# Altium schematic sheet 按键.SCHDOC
size A4
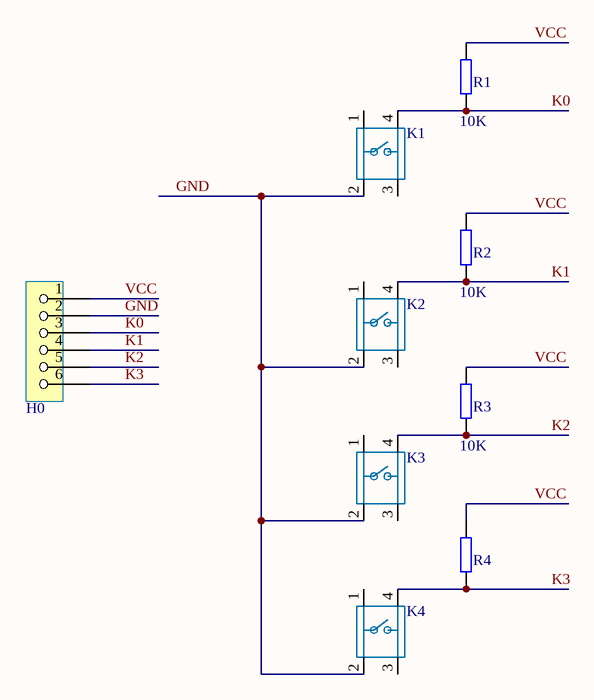
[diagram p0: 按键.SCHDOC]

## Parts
H0  DIS6  [DIS6]  (value not drawn)
K1  BUTTON  [BUTTON]  (value not drawn)
K2  BUTTON  [BUTTON]  (value not drawn)
K3  BUTTON  [BUTTON]  (value not drawn)
K4  BUTTON  [BUTTON]  (value not drawn)
R1  RESIS  [resistor-0.4]  (value not drawn)
R2  RESIS  [resistor-0.4]  (value not drawn)
R3  RESIS  [resistor-0.4]  (value not drawn)
R4  RESIS  [resistor-0.4]  (value not drawn)

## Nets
GND: H0.2 K1.2 K2.2 K3.2 K4.2
K0: H0.3 K1.4 R1.1
K1: H0.4 K2.4 R2.1
K2: H0.5 K3.4 R3.1
K3: H0.6 K4.4 R4.1
VCC: H0.1 R1.2 R2.2 R3.2 R4.2

Not connected (* = marked no-connect by the designer): K1 1 3; K2 1 3; K3 1 3; K4 1 3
